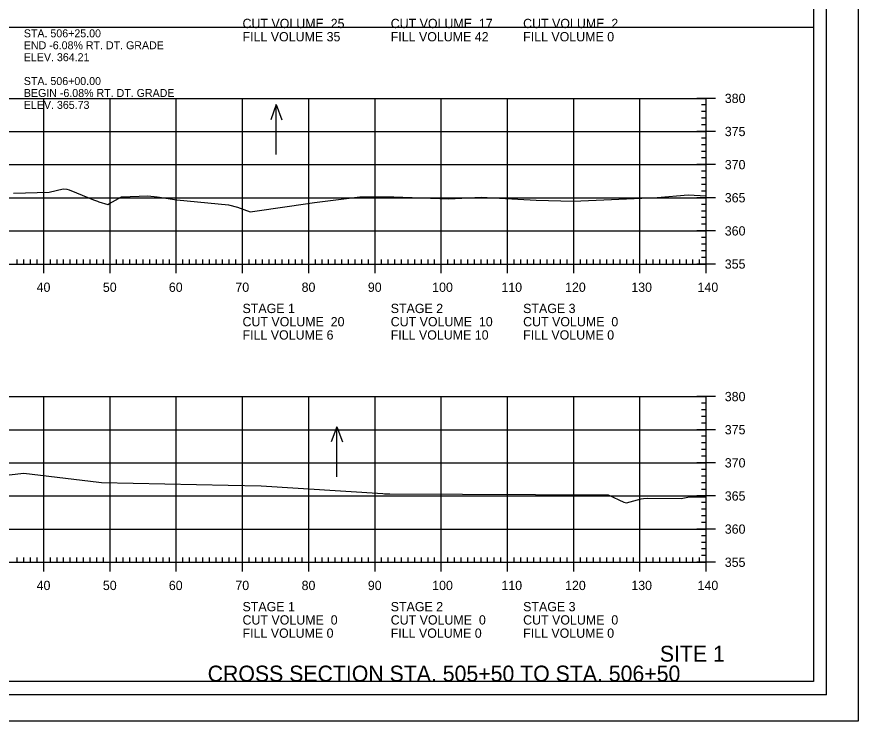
# Model space of a CAD drawing. Extents: x 1368910 to 1369601, y 380116 to 380950.
# Drawn here: x 1369116.2 to 1369243.2, y 380310.4 to 380416.7 of the extents above; entities that cross this region are included whole.
import ezdxf

# ---------------------------------------------------------------- set-up
doc = ezdxf.new("R2010")
doc.units = 0
for name, color, linetype in [('Notes', 7, 'Continuous'), ('R_Axis', 7, 'Continuous'), ('R_Axis Annot', 7, 'Continuous'), ('R_Border', 7, 'Continuous'), ('R_Draft', 7, 'Continuous'), ('R_Exist Surface', 7, 'Continuous'), ('R_Grid', 7, 'Continuous'), ('R_No Plot', 7, 'Continuous'), ('R_Water Annot', 7, 'Continuous')]:
    doc.layers.add(name, color=color, linetype=linetype)

msp = doc.modelspace()

# ---------------------------------------------------------------- linework, layer by layer
at = {"layer": 'R_Axis'}
for p, q in [((1369221.64, 380404.42), (1369218.84, 380404.42)), ((1369220.24, 380379.42), (1369220.24, 380404.42)), ((1369220.24, 380403.42), (1369219.54, 380403.42)), ((1369220.24, 380402.42), (1369219.54, 380402.42)), ((1369220.24, 380401.42), (1369219.54, 380401.42)), ((1369220.24, 380400.42), (1369219.54, 380400.42)), ((1369221.64, 380399.42), (1369218.84, 380399.42)), ((1369220.24, 380398.42), (1369219.54, 380398.42)), ((1369220.24, 380397.42), (1369219.54, 380397.42)), ((1369220.24, 380396.42), (1369219.54, 380396.42)), ((1369220.24, 380395.42), (1369219.54, 380395.42)), ((1369221.64, 380394.42), (1369218.84, 380394.42)), ((1369220.24, 380393.42), (1369219.54, 380393.42)), ((1369220.24, 380392.42), (1369219.54, 380392.42)), ((1369220.24, 380391.42), (1369219.54, 380391.42)), ((1369220.24, 380390.42), (1369219.54, 380390.42)), ((1369221.64, 380389.42), (1369218.84, 380389.42)), ((1369220.24, 380388.42), (1369219.54, 380388.42)), ((1369220.24, 380387.42), (1369219.54, 380387.42)), ((1369220.24, 380386.42), (1369219.54, 380386.42)), ((1369220.24, 380385.42), (1369219.54, 380385.42)), ((1369221.64, 380384.42), (1369218.84, 380384.42)), ((1369220.24, 380383.42), (1369219.54, 380383.42)), ((1369220.24, 380382.42), (1369219.54, 380382.42)), ((1369120.24, 380378.02), (1369120.24, 380380.82)), ((1369130.24, 380378.02), (1369130.24, 380380.82)), ((1369140.24, 380378.02), (1369140.24, 380380.82)), ((1369150.24, 380378.02), (1369150.24, 380380.82)), ((1369160.24, 380378.02), (1369160.24, 380380.82)), ((1369170.24, 380378.02), (1369170.24, 380380.82)), ((1369180.24, 380378.02), (1369180.24, 380380.82)), ((1369190.24, 380378.02), (1369190.24, 380380.82)), ((1369200.24, 380378.02), (1369200.24, 380380.82)), ((1369210.24, 380378.02), (1369210.24, 380380.82)), ((1369220.24, 380381.42), (1369219.54, 380381.42)), ((1369220.24, 380378.02), (1369220.24, 380380.82)), ((1368940.24, 380379.42), (1369220.24, 380379.42)), ((1369116.24, 380379.42), (1369116.24, 380380.12)), ((1369117.24, 380379.42), (1369117.24, 380380.12)), ((1369118.24, 380379.42), (1369118.24, 380380.12)), ((1369119.24, 380379.42), (1369119.24, 380380.12)), ((1369121.24, 380379.42), (1369121.24, 380380.12)), ((1369122.24, 380379.42), (1369122.24, 380380.12)), ((1369123.24, 380379.42), (1369123.24, 380380.12)), ((1369124.24, 380379.42), (1369124.24, 380380.12)), ((1369125.24, 380379.42), (1369125.24, 380380.12)), ((1369126.24, 380379.42), (1369126.24, 380380.12)), ((1369127.24, 380379.42), (1369127.24, 380380.12)), ((1369128.24, 380379.42), (1369128.24, 380380.12)), ((1369129.24, 380379.42), (1369129.24, 380380.12)), ((1369131.24, 380379.42), (1369131.24, 380380.12)), ((1369132.24, 380379.42), (1369132.24, 380380.12)), ((1369133.24, 380379.42), (1369133.24, 380380.12)), ((1369134.24, 380379.42), (1369134.24, 380380.12)), ((1369135.24, 380379.42), (1369135.24, 380380.12)), ((1369136.24, 380379.42), (1369136.24, 380380.12)), ((1369137.24, 380379.42), (1369137.24, 380380.12)), ((1369138.24, 380379.42), (1369138.24, 380380.12)), ((1369139.24, 380379.42), (1369139.24, 380380.12)), ((1369141.24, 380379.42), (1369141.24, 380380.12)), ((1369142.24, 380379.42), (1369142.24, 380380.12)), ((1369143.24, 380379.42), (1369143.24, 380380.12)), ((1369144.24, 380379.42), (1369144.24, 380380.12)), ((1369145.24, 380379.42), (1369145.24, 380380.12)), ((1369146.24, 380379.42), (1369146.24, 380380.12)), ((1369147.24, 380379.42), (1369147.24, 380380.12)), ((1369148.24, 380379.42), (1369148.24, 380380.12)), ((1369149.24, 380379.42), (1369149.24, 380380.12)), ((1369151.24, 380379.42), (1369151.24, 380380.12)), ((1369152.24, 380379.42), (1369152.24, 380380.12)), ((1369153.24, 380379.42), (1369153.24, 380380.12)), ((1369154.24, 380379.42), (1369154.24, 380380.12)), ((1369155.24, 380379.42), (1369155.24, 380380.12)), ((1369156.24, 380379.42), (1369156.24, 380380.12)), ((1369157.24, 380379.42), (1369157.24, 380380.12)), ((1369158.24, 380379.42), (1369158.24, 380380.12)), ((1369159.24, 380379.42), (1369159.24, 380380.12)), ((1369161.24, 380379.42), (1369161.24, 380380.12)), ((1369162.24, 380379.42), (1369162.24, 380380.12)), ((1369163.24, 380379.42), (1369163.24, 380380.12)), ((1369164.24, 380379.42), (1369164.24, 380380.12)), ((1369165.24, 380379.42), (1369165.24, 380380.12)), ((1369166.24, 380379.42), (1369166.24, 380380.12)), ((1369167.24, 380379.42), (1369167.24, 380380.12)), ((1369168.24, 380379.42), (1369168.24, 380380.12)), ((1369169.24, 380379.42), (1369169.24, 380380.12)), ((1369171.24, 380379.42), (1369171.24, 380380.12)), ((1369172.24, 380379.42), (1369172.24, 380380.12)), ((1369173.24, 380379.42), (1369173.24, 380380.12)), ((1369174.24, 380379.42), (1369174.24, 380380.12)), ((1369175.24, 380379.42), (1369175.24, 380380.12)), ((1369176.24, 380379.42), (1369176.24, 380380.12)), ((1369177.24, 380379.42), (1369177.24, 380380.12)), ((1369178.24, 380379.42), (1369178.24, 380380.12)), ((1369179.24, 380379.42), (1369179.24, 380380.12)), ((1369181.24, 380379.42), (1369181.24, 380380.12)), ((1369182.24, 380379.42), (1369182.24, 380380.12)), ((1369183.24, 380379.42), (1369183.24, 380380.12)), ((1369184.24, 380379.42), (1369184.24, 380380.12)), ((1369185.24, 380379.42), (1369185.24, 380380.12)), ((1369186.24, 380379.42), (1369186.24, 380380.12)), ((1369187.24, 380379.42), (1369187.24, 380380.12)), ((1369188.24, 380379.42), (1369188.24, 380380.12)), ((1369189.24, 380379.42), (1369189.24, 380380.12)), ((1369191.24, 380379.42), (1369191.24, 380380.12)), ((1369192.24, 380379.42), (1369192.24, 380380.12)), ((1369193.24, 380379.42), (1369193.24, 380380.12)), ((1369194.24, 380379.42), (1369194.24, 380380.12)), ((1369195.24, 380379.42), (1369195.24, 380380.12)), ((1369196.24, 380379.42), (1369196.24, 380380.12)), ((1369197.24, 380379.42), (1369197.24, 380380.12)), ((1369198.24, 380379.42), (1369198.24, 380380.12)), ((1369199.24, 380379.42), (1369199.24, 380380.12)), ((1369201.24, 380379.42), (1369201.24, 380380.12)), ((1369202.24, 380379.42), (1369202.24, 380380.12)), ((1369203.24, 380379.42), (1369203.24, 380380.12)), ((1369204.24, 380379.42), (1369204.24, 380380.12)), ((1369205.24, 380379.42), (1369205.24, 380380.12)), ((1369206.24, 380379.42), (1369206.24, 380380.12)), ((1369207.24, 380379.42), (1369207.24, 380380.12)), ((1369208.24, 380379.42), (1369208.24, 380380.12)), ((1369209.24, 380379.42), (1369209.24, 380380.12)), ((1369211.24, 380379.42), (1369211.24, 380380.12)), ((1369212.24, 380379.42), (1369212.24, 380380.12)), ((1369213.24, 380379.42), (1369213.24, 380380.12)), ((1369214.24, 380379.42), (1369214.24, 380380.12)), ((1369215.24, 380379.42), (1369215.24, 380380.12)), ((1369216.24, 380379.42), (1369216.24, 380380.12)), ((1369217.24, 380379.42), (1369217.24, 380380.12)), ((1369218.24, 380379.42), (1369218.24, 380380.12)), ((1369221.64, 380379.42), (1369218.84, 380379.42)), ((1369219.24, 380379.42), (1369219.24, 380380.12)), ((1369220.24, 380380.42), (1369219.54, 380380.42)), ((1369221.64, 380359.42), (1369218.84, 380359.42)), ((1369220.24, 380334.42), (1369220.24, 380359.42)), ((1369220.24, 380358.42), (1369219.54, 380358.42)), ((1369220.24, 380357.42), (1369219.54, 380357.42)), ((1369220.24, 380356.42), (1369219.54, 380356.42)), ((1369220.24, 380355.42), (1369219.54, 380355.42)), ((1369221.64, 380354.42), (1369218.84, 380354.42)), ((1369220.24, 380353.42), (1369219.54, 380353.42)), ((1369220.24, 380352.42), (1369219.54, 380352.42)), ((1369220.24, 380351.42), (1369219.54, 380351.42)), ((1369220.24, 380350.42), (1369219.54, 380350.42)), ((1369221.64, 380349.42), (1369218.84, 380349.42)), ((1369220.24, 380348.42), (1369219.54, 380348.42)), ((1369220.24, 380347.42), (1369219.54, 380347.42)), ((1369220.24, 380346.42), (1369219.54, 380346.42)), ((1369220.24, 380345.42), (1369219.54, 380345.42)), ((1369221.64, 380344.42), (1369218.84, 380344.42)), ((1369220.24, 380343.42), (1369219.54, 380343.42)), ((1369220.24, 380342.42), (1369219.54, 380342.42)), ((1369220.24, 380341.42), (1369219.54, 380341.42)), ((1369220.24, 380340.42), (1369219.54, 380340.42)), ((1369221.64, 380339.42), (1369218.84, 380339.42)), ((1369220.24, 380338.42), (1369219.54, 380338.42)), ((1369220.24, 380337.42), (1369219.54, 380337.42)), ((1369220.24, 380336.42), (1369219.54, 380336.42)), ((1369116.24, 380334.42), (1369116.24, 380335.12)), ((1369117.24, 380334.42), (1369117.24, 380335.12)), ((1369118.24, 380334.42), (1369118.24, 380335.12)), ((1369119.24, 380334.42), (1369119.24, 380335.12)), ((1369120.24, 380333.02), (1369120.24, 380335.82)), ((1369121.24, 380334.42), (1369121.24, 380335.12)), ((1369122.24, 380334.42), (1369122.24, 380335.12)), ((1369123.24, 380334.42), (1369123.24, 380335.12)), ((1369124.24, 380334.42), (1369124.24, 380335.12)), ((1369125.24, 380334.42), (1369125.24, 380335.12)), ((1369126.24, 380334.42), (1369126.24, 380335.12)), ((1369127.24, 380334.42), (1369127.24, 380335.12)), ((1369128.24, 380334.42), (1369128.24, 380335.12)), ((1369129.24, 380334.42), (1369129.24, 380335.12)), ((1369130.24, 380333.02), (1369130.24, 380335.82)), ((1369131.24, 380334.42), (1369131.24, 380335.12)), ((1369132.24, 380334.42), (1369132.24, 380335.12)), ((1369133.24, 380334.42), (1369133.24, 380335.12)), ((1369134.24, 380334.42), (1369134.24, 380335.12)), ((1369135.24, 380334.42), (1369135.24, 380335.12)), ((1369136.24, 380334.42), (1369136.24, 380335.12)), ((1369137.24, 380334.42), (1369137.24, 380335.12)), ((1369138.24, 380334.42), (1369138.24, 380335.12)), ((1369139.24, 380334.42), (1369139.24, 380335.12)), ((1369140.24, 380333.02), (1369140.24, 380335.82)), ((1369141.24, 380334.42), (1369141.24, 380335.12)), ((1369142.24, 380334.42), (1369142.24, 380335.12)), ((1369143.24, 380334.42), (1369143.24, 380335.12)), ((1369144.24, 380334.42), (1369144.24, 380335.12)), ((1369145.24, 380334.42), (1369145.24, 380335.12)), ((1369146.24, 380334.42), (1369146.24, 380335.12)), ((1369147.24, 380334.42), (1369147.24, 380335.12)), ((1369148.24, 380334.42), (1369148.24, 380335.12)), ((1369149.24, 380334.42), (1369149.24, 380335.12)), ((1369150.24, 380333.02), (1369150.24, 380335.82)), ((1369151.24, 380334.42), (1369151.24, 380335.12)), ((1369152.24, 380334.42), (1369152.24, 380335.12)), ((1369153.24, 380334.42), (1369153.24, 380335.12)), ((1369154.24, 380334.42), (1369154.24, 380335.12)), ((1369155.24, 380334.42), (1369155.24, 380335.12)), ((1369156.24, 380334.42), (1369156.24, 380335.12)), ((1369157.24, 380334.42), (1369157.24, 380335.12)), ((1369158.24, 380334.42), (1369158.24, 380335.12)), ((1369159.24, 380334.42), (1369159.24, 380335.12)), ((1369160.24, 380333.02), (1369160.24, 380335.82)), ((1369161.24, 380334.42), (1369161.24, 380335.12)), ((1369162.24, 380334.42), (1369162.24, 380335.12)), ((1369163.24, 380334.42), (1369163.24, 380335.12)), ((1369164.24, 380334.42), (1369164.24, 380335.12)), ((1369165.24, 380334.42), (1369165.24, 380335.12)), ((1369166.24, 380334.42), (1369166.24, 380335.12)), ((1369167.24, 380334.42), (1369167.24, 380335.12)), ((1369168.24, 380334.42), (1369168.24, 380335.12)), ((1369169.24, 380334.42), (1369169.24, 380335.12)), ((1369170.24, 380333.02), (1369170.24, 380335.82)), ((1369171.24, 380334.42), (1369171.24, 380335.12)), ((1369172.24, 380334.42), (1369172.24, 380335.12)), ((1369173.24, 380334.42), (1369173.24, 380335.12)), ((1369174.24, 380334.42), (1369174.24, 380335.12)), ((1369175.24, 380334.42), (1369175.24, 380335.12)), ((1369176.24, 380334.42), (1369176.24, 380335.12)), ((1369177.24, 380334.42), (1369177.24, 380335.12)), ((1369178.24, 380334.42), (1369178.24, 380335.12)), ((1369179.24, 380334.42), (1369179.24, 380335.12)), ((1369180.24, 380333.02), (1369180.24, 380335.82)), ((1369181.24, 380334.42), (1369181.24, 380335.12)), ((1369182.24, 380334.42), (1369182.24, 380335.12)), ((1369183.24, 380334.42), (1369183.24, 380335.12)), ((1369184.24, 380334.42), (1369184.24, 380335.12)), ((1369185.24, 380334.42), (1369185.24, 380335.12)), ((1369186.24, 380334.42), (1369186.24, 380335.12)), ((1369187.24, 380334.42), (1369187.24, 380335.12)), ((1369188.24, 380334.42), (1369188.24, 380335.12)), ((1369189.24, 380334.42), (1369189.24, 380335.12)), ((1369190.24, 380333.02), (1369190.24, 380335.82)), ((1369191.24, 380334.42), (1369191.24, 380335.12)), ((1369192.24, 380334.42), (1369192.24, 380335.12)), ((1369193.24, 380334.42), (1369193.24, 380335.12)), ((1369194.24, 380334.42), (1369194.24, 380335.12)), ((1369195.24, 380334.42), (1369195.24, 380335.12)), ((1369196.24, 380334.42), (1369196.24, 380335.12)), ((1369197.24, 380334.42), (1369197.24, 380335.12)), ((1369198.24, 380334.42), (1369198.24, 380335.12)), ((1369199.24, 380334.42), (1369199.24, 380335.12)), ((1369200.24, 380333.02), (1369200.24, 380335.82)), ((1369201.24, 380334.42), (1369201.24, 380335.12)), ((1369202.24, 380334.42), (1369202.24, 380335.12)), ((1369203.24, 380334.42), (1369203.24, 380335.12)), ((1369204.24, 380334.42), (1369204.24, 380335.12)), ((1369205.24, 380334.42), (1369205.24, 380335.12)), ((1369206.24, 380334.42), (1369206.24, 380335.12)), ((1369207.24, 380334.42), (1369207.24, 380335.12)), ((1369208.24, 380334.42), (1369208.24, 380335.12)), ((1369209.24, 380334.42), (1369209.24, 380335.12)), ((1369210.24, 380333.02), (1369210.24, 380335.82)), ((1369211.24, 380334.42), (1369211.24, 380335.12)), ((1369212.24, 380334.42), (1369212.24, 380335.12)), ((1369213.24, 380334.42), (1369213.24, 380335.12)), ((1369214.24, 380334.42), (1369214.24, 380335.12)), ((1369215.24, 380334.42), (1369215.24, 380335.12)), ((1369216.24, 380334.42), (1369216.24, 380335.12)), ((1369217.24, 380334.42), (1369217.24, 380335.12)), ((1369218.24, 380334.42), (1369218.24, 380335.12)), ((1369219.24, 380334.42), (1369219.24, 380335.12)), ((1369220.24, 380335.42), (1369219.54, 380335.42)), ((1369220.24, 380333.02), (1369220.24, 380335.82)), ((1368940.24, 380334.42), (1369220.24, 380334.42)), ((1369221.64, 380334.42), (1369218.84, 380334.42))]:
    msp.add_line(p, q, dxfattribs=at)
at = {"layer": 'R_Border'}
for q in [(1369238.42, 380519.88), (1368922.24, 380314.42)]:
    msp.add_line((1369238.42, 380314.42), q, dxfattribs=at)
at = {"layer": 'R_Exist Surface'}
for points in [[(1369115.67, 380390.1), (1369121.04, 380390.24), (1369123.19, 380390.76), (1369123.73, 380390.74), (1369124.07, 380390.62), (1369125.2, 380390.14), (1369127.72, 380389.11), (1369128.33, 380388.92), (1369128.57, 380388.83), (1369129.89, 380388.38), (1369130.16, 380388.54), (1369131.99, 380389.57), (1369135.96, 380389.72), (1369137.34, 380389.57), (1369140.31, 380389.12), (1369148.13, 380388.37), (1369149.47, 380387.98), (1369151.37, 380387.28), (1369157.31, 380388.16), (1369161.1, 380388.69), (1369167.96, 380389.56), (1369173.06, 380389.55), (1369181.39, 380389.25), (1369186.24, 380389.53), (1369194.58, 380389.08), (1369200.17, 380388.92), (1369212.84, 380389.48), (1369217.51, 380389.84), (1369220.24, 380389.7)], [(1369114.99, 380347.6), (1369117.24, 380347.87), (1369128.53, 380346.5), (1369128.95, 380346.46), (1369148.07, 380346.03), (1369153.07, 380345.93), (1369171.42, 380344.77), (1369171.66, 380344.75), (1369171.94, 380344.73), (1369172.42, 380344.75), (1369172.46, 380344.75), (1369205.46, 380344.61), (1369207.8, 380343.5), (1369208.22, 380343.37), (1369210.4, 380344.01), (1369210.77, 380344.06), (1369211.31, 380344.09), (1369216.45, 380344.05), (1369217.7, 380344.28), (1369218.96, 380344.29), (1369220.24, 380344.24)]]:
    msp.add_lwpolyline(points, dxfattribs=at)
at = {"layer": 'R_Grid'}
for p, q in [((1368940.24, 380404.42), (1369220.24, 380404.42)), ((1369120.24, 380379.42), (1369120.24, 380404.42)), ((1369130.24, 380379.42), (1369130.24, 380404.42)), ((1369140.24, 380379.42), (1369140.24, 380404.42)), ((1369150.24, 380379.42), (1369150.24, 380404.42)), ((1369160.24, 380379.42), (1369160.24, 380404.42)), ((1369170.24, 380379.42), (1369170.24, 380404.42)), ((1369180.24, 380379.42), (1369180.24, 380404.42)), ((1369190.24, 380379.42), (1369190.24, 380404.42)), ((1369200.24, 380379.42), (1369200.24, 380404.42)), ((1369210.24, 380379.42), (1369210.24, 380404.42)), ((1369220.24, 380379.42), (1369220.24, 380404.42)), ((1368940.24, 380399.42), (1369220.24, 380399.42)), ((1368940.24, 380394.42), (1369220.24, 380394.42)), ((1368940.24, 380389.42), (1369220.24, 380389.42)), ((1368940.24, 380384.42), (1369220.24, 380384.42)), ((1368940.24, 380379.42), (1369220.24, 380379.42)), ((1368940.24, 380359.42), (1369220.24, 380359.42)), ((1369120.24, 380334.42), (1369120.24, 380359.42)), ((1369130.24, 380334.42), (1369130.24, 380359.42)), ((1369140.24, 380334.42), (1369140.24, 380359.42)), ((1369150.24, 380334.42), (1369150.24, 380359.42)), ((1369160.24, 380334.42), (1369160.24, 380359.42)), ((1369170.24, 380334.42), (1369170.24, 380359.42)), ((1369180.24, 380334.42), (1369180.24, 380359.42)), ((1369190.24, 380334.42), (1369190.24, 380359.42)), ((1369200.24, 380334.42), (1369200.24, 380359.42)), ((1369210.24, 380334.42), (1369210.24, 380359.42)), ((1369220.24, 380334.42), (1369220.24, 380359.42)), ((1368940.24, 380354.42), (1369220.24, 380354.42)), ((1368940.24, 380349.42), (1369220.24, 380349.42)), ((1368940.24, 380344.42), (1369220.24, 380344.42)), ((1368940.24, 380339.42), (1369220.24, 380339.42)), ((1368940.24, 380334.42), (1369220.24, 380334.42))]:
    msp.add_line(p, q, dxfattribs=at)
at = {"layer": 'R_No Plot'}
for points in [[(1368909.84, 380523.78), (1369243.18, 380523.78), (1369243.18, 380310.44), (1368909.84, 380310.44)], [(1368924.24, 380517.88), (1369173.78, 380517.88), (1369173.78, 380508), (1369191.32, 380508), (1369215.42, 380508), (1369215.42, 380485.67), (1369236.42, 380485.67), (1369236.42, 380316.42), (1368924.24, 380316.42)], [(1368924.24, 380415.15), (1369236.42, 380415.15), (1369236.42, 380316.42), (1368924.24, 380316.42)]]:
    msp.add_lwpolyline(points, close=True, dxfattribs=at)
at = {"layer": 'R_Water Annot'}
for p, q in [((1369155.33, 380403.5), (1369154.49, 380401.19)), ((1369155.33, 380395.96), (1369155.33, 380403.5)), ((1369155.33, 380403.5), (1369156.17, 380401.19)), ((1369164.47, 380354.87), (1369163.63, 380352.57)), ((1369164.47, 380347.33), (1369164.47, 380354.87)), ((1369164.47, 380354.87), (1369165.31, 380352.57))]:
    msp.add_line(p, q, dxfattribs=at)

# ---------------------------------------------------------------- texts
at = {"layer": 'Notes'}
for s, p in [('STA. 506+25.00', (1369117.23, 380413.63)), ('END -6.08% RT. DT. GRADE', (1369117.23, 380411.83)), ('ELEV. 364.21', (1369117.23, 380410.03)), ('STA. 506+00.00', (1369117.23, 380406.43)), ('BEGIN -6.08% RT. DT. GRADE', (1369117.23, 380404.63)), ('ELEV. 365.73', (1369117.23, 380402.83))]:
    msp.add_text(s, height=1.2, dxfattribs=at).set_placement(p)
at = {"layer": 'R_Axis Annot'}
for s, p in [('CUT VOLUME  25', (1369150.24, 380415.02)), ('CUT VOLUME  17', (1369172.61, 380415.02)), ('CUT VOLUME  2', (1369192.6, 380415.02)), ('FILL VOLUME 35', (1369150.24, 380413.02)), ('FILL VOLUME 42', (1369172.61, 380413.02)), ('FILL VOLUME 0', (1369192.6, 380413.02)), ('380', (1369223.04, 380403.72)), ('375', (1369223.04, 380398.72)), ('370', (1369223.04, 380393.72)), ('365', (1369223.04, 380388.72)), ('360', (1369223.04, 380383.72)), ('355', (1369223.04, 380378.72)), ('40', (1369119.16, 380375.22)), ('50', (1369129.16, 380375.22)), ('60', (1369139.12, 380375.22)), ('70', (1369149.16, 380375.22)), ('80', (1369159.16, 380375.22)), ('90', (1369169.16, 380375.22)), ('100', (1369178.87, 380375.22)), ('110', (1369189.32, 380375.22)), ('120', (1369198.93, 380375.22)), ('130', (1369208.93, 380375.22)), ('140', (1369218.93, 380375.22)), ('STAGE 1', (1369150.24, 380372.02)), ('STAGE 2', (1369172.61, 380372.02)), ('STAGE 3', (1369192.6, 380372.02)), ('CUT VOLUME  20', (1369150.24, 380370.02)), ('CUT VOLUME  10', (1369172.61, 380370.02)), ('CUT VOLUME  0', (1369192.6, 380370.02)), ('FILL VOLUME 6', (1369150.24, 380368.02)), ('FILL VOLUME 10', (1369172.61, 380368.02)), ('FILL VOLUME 0', (1369192.6, 380368.02)), ('380', (1369223.04, 380358.72)), ('375', (1369223.04, 380353.72)), ('370', (1369223.04, 380348.72)), ('365', (1369223.04, 380343.72)), ('360', (1369223.04, 380338.72)), ('355', (1369223.04, 380333.72)), ('40', (1369119.16, 380330.22)), ('50', (1369129.16, 380330.22)), ('60', (1369139.12, 380330.22)), ('70', (1369149.16, 380330.22)), ('80', (1369159.16, 380330.22)), ('90', (1369169.16, 380330.22)), ('100', (1369178.87, 380330.22)), ('110', (1369189.32, 380330.22)), ('120', (1369198.93, 380330.22)), ('130', (1369208.93, 380330.22)), ('140', (1369218.93, 380330.22)), ('STAGE 1', (1369150.24, 380327.02)), ('STAGE 2', (1369172.61, 380327.02)), ('STAGE 3', (1369192.6, 380327.02)), ('CUT VOLUME  0', (1369150.24, 380325.02)), ('CUT VOLUME  0', (1369172.61, 380325.02)), ('CUT VOLUME  0', (1369192.6, 380325.02)), ('FILL VOLUME 0', (1369150.24, 380323.02)), ('FILL VOLUME 0', (1369172.61, 380323.02)), ('FILL VOLUME 0', (1369192.6, 380323.02))]:
    msp.add_text(s, height=1.4, dxfattribs=at).set_placement(p)
at = {"layer": 'R_Draft'}
for s, p in [('SITE 1', (1369213.24, 380319.42)), ('CROSS SECTION STA. 505+50 TO STA. 506+50', (1369144.98, 380316.42))]:
    msp.add_text(s, height=2.4, dxfattribs=at).set_placement(p)

doc.saveas('drawing.dxf')
